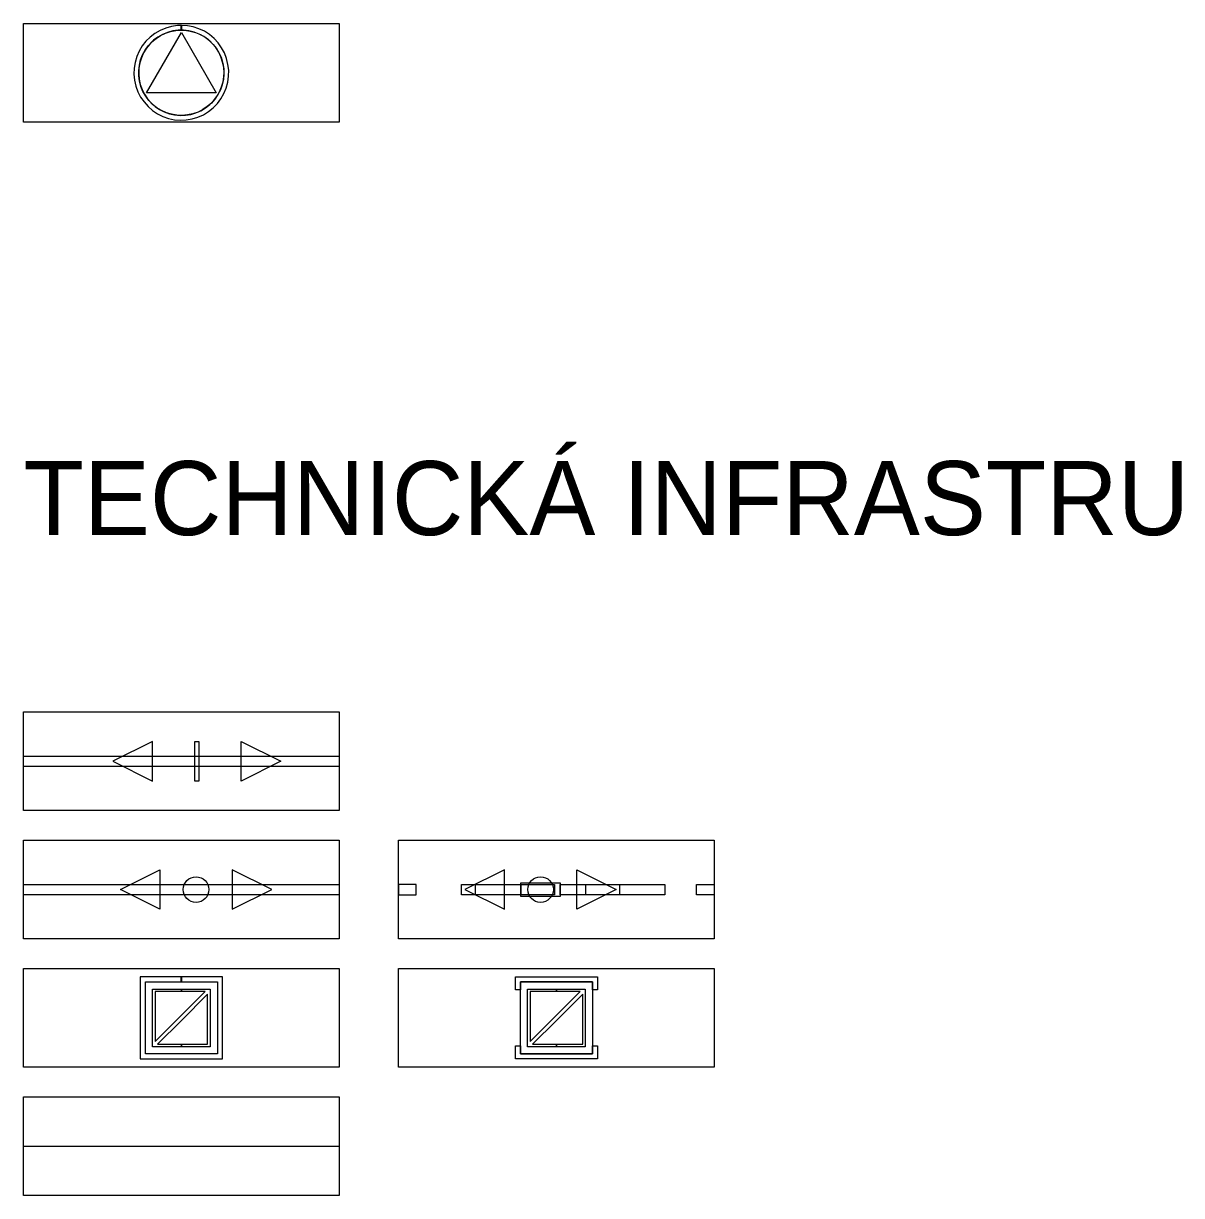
# Model space of a CAD drawing. Extents: x -477645 to -464995, y -1159281 to -1149080.
# Drawn here: x -466094.7 to -465801.3, y -1156175.7 to -1155878.8 of the extents above; entities that cross this region are included whole.
import ezdxf

# ---------------------------------------------------------------- set-up
doc = ezdxf.new("R2010")
doc.units = 0
for name, color, linetype in [('ložisk_nerost', 7, 'Continuous'), ('OP', 7, 'Continuous'), ('TRAFOSTANICE', 7, 'Continuous'), ('VN VZDUŠNÉ', 7, 'Continuous'), ('Vrstva 22_místní_vodovod_návrh', 7, 'Continuous'), ('Vrstva 60', 7, 'Continuous')]:
    doc.layers.add(name, color=color, linetype=linetype)

msp = doc.modelspace()

# ---------------------------------------------------------------- linework, layer by layer
at = {"layer": 'ložisk_nerost'}
for points in [[(-466054.7, -1155879.28), (-466055.7, -1155879.33), (-466057.2, -1155879.55), (-466058.66, -1155879.96), (-466060.06, -1155880.55), (-466061.37, -1155881.31), (-466062.58, -1155882.24), (-466063.66, -1155883.3), (-466064.59, -1155884.5), (-466065.37, -1155885.8), (-466065.98, -1155887.19), (-466066.41, -1155888.65), (-466066.65, -1155890.15), (-466066.69, -1155891.66), (-466066.55, -1155893.18), (-466066.22, -1155894.66), (-466065.7, -1155896.09), (-466065.01, -1155897.44), (-466064.15, -1155898.69), (-466063.14, -1155899.82), (-466062, -1155900.82), (-466060.74, -1155901.67), (-466059.38, -1155902.35), (-466057.95, -1155902.85), (-466056.46, -1155903.17), (-466054.95, -1155903.3), (-466053.44, -1155903.23), (-466051.94, -1155902.98), (-466050.49, -1155902.54), (-466049.1, -1155901.92), (-466047.8, -1155901.13), (-466046.62, -1155900.18), (-466045.56, -1155899.09), (-466044.65, -1155897.88), (-466043.9, -1155896.56), (-466043.32, -1155895.15), (-466042.93, -1155893.69), (-466042.72, -1155892.18), (-466042.7, -1155890.67), (-466042.88, -1155889.16), (-466043.24, -1155887.68), (-466043.79, -1155886.27), (-466044.51, -1155884.93), (-466045.39, -1155883.7), (-466046.42, -1155882.58), (-466047.59, -1155881.61), (-466048.87, -1155880.79), (-466050.24, -1155880.14), (-466051.68, -1155879.67), (-466053.17, -1155879.38), (-466054.69, -1155879.28)], [(-466043.88, -1155891.29), (-466043.97, -1155889.93), (-466044.23, -1155888.59), (-466044.65, -1155887.29), (-466045.24, -1155886.05), (-466045.98, -1155884.9), (-466046.85, -1155883.85), (-466047.85, -1155882.92), (-466048.96, -1155882.13), (-466050.17, -1155881.48), (-466051.44, -1155880.99), (-466052.77, -1155880.66), (-466054.12, -1155880.5), (-466055.49, -1155880.51), (-466056.84, -1155880.7), (-466058.16, -1155881.06), (-466059.43, -1155881.58), (-466060.61, -1155882.25), (-466061.71, -1155883.07), (-466062.69, -1155884.02), (-466063.54, -1155885.09), (-466064.25, -1155886.26), (-466064.81, -1155887.5), (-466065.21, -1155888.81), (-466065.44, -1155890.16), (-466065.5, -1155891.52), (-466065.38, -1155892.88), (-466065.1, -1155894.22), (-466064.64, -1155895.51), (-466064.03, -1155896.73), (-466063.27, -1155897.87), (-466062.37, -1155898.9), (-466061.35, -1155899.8), (-466060.23, -1155900.58), (-466059.01, -1155901.2), (-466057.73, -1155901.67), (-466056.39, -1155901.97), (-466055.03, -1155902.1), (-466053.67, -1155902.05), (-466052.32, -1155901.84), (-466051.01, -1155901.45), (-466049.75, -1155900.91), (-466048.58, -1155900.21), (-466047.5, -1155899.36), (-466046.54, -1155898.39), (-466045.71, -1155897.31), (-466045.03, -1155896.13), (-466044.49, -1155894.87), (-466044.12, -1155893.55), (-466043.92, -1155892.2), (-466043.88, -1155891.29)], [(-466054.69, -1155880.48), (-466053.79, -1155880.52), (-466052.44, -1155880.72), (-466051.12, -1155881.09), (-466049.86, -1155881.62), (-466048.68, -1155882.31), (-466047.6, -1155883.14), (-466046.63, -1155884.1), (-466045.78, -1155885.18), (-466045.08, -1155886.35), (-466044.53, -1155887.6), (-466044.15, -1155888.91), (-466043.93, -1155890.26), (-466043.89, -1155891.63), (-466044.02, -1155892.99), (-466044.32, -1155894.32), (-466044.78, -1155895.61), (-466045.41, -1155896.82), (-466046.18, -1155897.95), (-466047.09, -1155898.97), (-466048.12, -1155899.87), (-466049.25, -1155900.63), (-466050.47, -1155901.24), (-466051.76, -1155901.7), (-466053.1, -1155901.98), (-466054.46, -1155902.1), (-466055.82, -1155902.04), (-466057.17, -1155901.81), (-466058.48, -1155901.42), (-466059.73, -1155900.86), (-466060.89, -1155900.15), (-466061.96, -1155899.29), (-466062.91, -1155898.31), (-466063.73, -1155897.22), (-466064.41, -1155896.03), (-466064.93, -1155894.77), (-466065.28, -1155893.45), (-466065.47, -1155892.1), (-466065.49, -1155890.73), (-466065.33, -1155889.37), (-466065, -1155888.04), (-466064.51, -1155886.77), (-466063.86, -1155885.57), (-466063.06, -1155884.46), (-466062.13, -1155883.46), (-466061.09, -1155882.58), (-466059.94, -1155881.84), (-466058.7, -1155881.26), (-466057.4, -1155880.83), (-466056.06, -1155880.57), (-466054.7, -1155880.48)], [(-466054.69, -1155881.13), (-466045.89, -1155896.37), (-466063.49, -1155896.37), (-466054.69, -1155881.13)], [(-466054.7, -1155880.48), (-466054.7, -1155879.28)], [(-466054.69, -1155879.28), (-466054.69, -1155880.48)], [(-465970.09, -1156123.61), (-465970.09, -1156120.28)], [(-465970.09, -1156120.28), (-465952.62, -1156120.28)], [(-465968.81, -1156121.56), (-465950.57, -1156121.56), (-465950.57, -1156139.8), (-465968.81, -1156139.8), (-465968.81, -1156121.56)], [(-465952.62, -1156121.56), (-465968.81, -1156121.56), (-465968.81, -1156123.61)], [(-465952.62, -1156120.28), (-465949.29, -1156120.28), (-465949.29, -1156123.61)], [(-465950.57, -1156123.61), (-465950.57, -1156121.56), (-465952.62, -1156121.56)], [(-465968.81, -1156123.61), (-465970.09, -1156123.61)], [(-465966.98, -1156130.68), (-465966.98, -1156123.39), (-465959.69, -1156123.39)], [(-465959.69, -1156124.02), (-465966.35, -1156124.02)], [(-465966.35, -1156124.02), (-465966.35, -1156130.68)], [(-465960.33, -1156130.68), (-465953.67, -1156124.02)], [(-465959.69, -1156123.39), (-465959.69, -1156124.02)], [(-465953.03, -1156124.66), (-465959.69, -1156131.32)], [(-465959.66, -1156124.02), (-465959.66, -1156123.39)], [(-465959.66, -1156123.39), (-465952.4, -1156123.39), (-465952.4, -1156130.68)], [(-465953.67, -1156124.02), (-465959.66, -1156124.02)], [(-465953.03, -1156130.68), (-465953.03, -1156124.66)], [(-465949.29, -1156123.61), (-465950.57, -1156123.61)], [(-465959.69, -1156137.97), (-465966.98, -1156137.97), (-465966.98, -1156130.68)], [(-465966.35, -1156130.68), (-465966.35, -1156136.69)], [(-465966.35, -1156136.69), (-465960.33, -1156130.68)], [(-465952.4, -1156130.68), (-465952.4, -1156137.97), (-465959.66, -1156137.97)], [(-465953.03, -1156137.34), (-465953.03, -1156130.68)], [(-465959.69, -1156131.32), (-465965.71, -1156137.34)], [(-465966.76, -1156141.08), (-465970.09, -1156141.08), (-465970.09, -1156137.75)], [(-465970.09, -1156137.75), (-465968.81, -1156137.75)], [(-465968.81, -1156137.75), (-465968.81, -1156139.8), (-465952.62, -1156139.8)], [(-465949.29, -1156137.75), (-465949.29, -1156141.08), (-465966.76, -1156141.08)], [(-465965.71, -1156137.34), (-465959.69, -1156137.34)], [(-465959.69, -1156137.34), (-465959.69, -1156137.97)], [(-465959.66, -1156137.34), (-465953.03, -1156137.34)], [(-465959.66, -1156137.97), (-465959.66, -1156137.34)], [(-465952.62, -1156139.8), (-465950.57, -1156139.8), (-465950.57, -1156137.75)], [(-465950.57, -1156137.75), (-465949.29, -1156137.75)]]:
    msp.add_lwpolyline(points, dxfattribs=at)
at = {"layer": 'OP'}
msp.add_line((-466094.69, -1156163.18), (-466014.69, -1156163.18), dxfattribs=at)
at = {"layer": 'TRAFOSTANICE'}
for points in [[(-466054.72, -1156120.28), (-466065.09, -1156120.28), (-466065.09, -1156141.08), (-466044.29, -1156141.08), (-466044.29, -1156120.28), (-466054.69, -1156120.28)], [(-466063.81, -1156121.56), (-466045.57, -1156121.56), (-466045.57, -1156139.8), (-466063.81, -1156139.8), (-466063.81, -1156121.56)], [(-466054.69, -1156121.56), (-466045.57, -1156121.56), (-466045.57, -1156139.8), (-466063.81, -1156139.8), (-466063.81, -1156121.56), (-466054.72, -1156121.56)], [(-466054.72, -1156121.56), (-466054.72, -1156120.28)], [(-466054.69, -1156120.28), (-466054.69, -1156121.56)], [(-466061.98, -1156130.68), (-466061.98, -1156123.39), (-466054.69, -1156123.39)], [(-466054.69, -1156124.02), (-466061.35, -1156124.02)], [(-466061.35, -1156124.02), (-466061.35, -1156130.68)], [(-466055.33, -1156130.68), (-466048.68, -1156124.02)], [(-466054.69, -1156123.39), (-466054.69, -1156124.02)], [(-466048.03, -1156124.66), (-466054.69, -1156131.32)], [(-466054.66, -1156124.02), (-466054.66, -1156123.39)], [(-466054.66, -1156123.39), (-466047.4, -1156123.39), (-466047.4, -1156130.68)], [(-466048.68, -1156124.02), (-466054.66, -1156124.02)], [(-466048.03, -1156130.68), (-466048.03, -1156124.66)], [(-466054.69, -1156137.97), (-466061.98, -1156137.97), (-466061.98, -1156130.68)], [(-466061.35, -1156130.68), (-466061.35, -1156136.7)], [(-466061.35, -1156136.7), (-466055.33, -1156130.68)], [(-466047.4, -1156130.68), (-466047.4, -1156137.97), (-466054.66, -1156137.97)], [(-466048.03, -1156137.34), (-466048.03, -1156130.68)], [(-466054.69, -1156131.32), (-466060.71, -1156137.34)], [(-466060.71, -1156137.34), (-466054.69, -1156137.34)], [(-466054.69, -1156137.34), (-466054.69, -1156137.97)], [(-466054.66, -1156137.34), (-466048.03, -1156137.34)], [(-466054.66, -1156137.97), (-466054.66, -1156137.34)]]:
    msp.add_lwpolyline(points, dxfattribs=at)
at = {"layer": 'VN VZDUŠNÉ'}
for p, q in [((-466062.03, -1156060.68), (-466072.03, -1156065.68)), ((-466062.03, -1156070.68), (-466062.03, -1156060.68)), ((-466039.53, -1156070.68), (-466039.53, -1156060.68)), ((-466039.53, -1156060.68), (-466029.53, -1156065.68)), ((-466072.03, -1156065.68), (-466062.03, -1156070.68)), ((-466029.53, -1156065.68), (-466039.53, -1156070.68))]:
    msp.add_line(p, q, dxfattribs=at)
for points in [[(-466050.28, -1156060.68), (-466050.28, -1156070.68), (-466051.28, -1156070.68)], [(-466051.28, -1156070.68), (-466051.28, -1156060.68)], [(-466051.28, -1156060.68), (-466050.28, -1156060.68)]]:
    msp.add_lwpolyline(points, dxfattribs=at)
msp.add_lwpolyline([(-466014.69, -1156066.98), (-466094.69, -1156066.98), (-466094.69, -1156064.38), (-466014.69, -1156064.38)], close=True, dxfattribs=at)
at = {"layer": 'Vrstva 22_místní_vodovod_návrh'}
for p, q in [((-466070.14, -1156098.18), (-466060.14, -1156093.18)), ((-466060.14, -1156093.18), (-466060.14, -1156103.18)), ((-466031.8, -1156098.18), (-466041.8, -1156093.18)), ((-466041.8, -1156093.18), (-466041.8, -1156103.18)), ((-465972.87, -1156093.18), (-465982.87, -1156098.18)), ((-465972.87, -1156103.18), (-465972.87, -1156093.18)), ((-465954.54, -1156103.18), (-465954.54, -1156093.18)), ((-465954.54, -1156093.18), (-465944.54, -1156098.18)), ((-466060.14, -1156103.18), (-466070.14, -1156098.18)), ((-466041.8, -1156103.18), (-466031.8, -1156098.18)), ((-465982.87, -1156098.18), (-465972.87, -1156103.18)), ((-465944.54, -1156098.18), (-465954.54, -1156103.18))]:
    msp.add_line(p, q, dxfattribs=at)
for points in [[(-466094.69, -1156096.88), (-466014.69, -1156096.88), (-466014.69, -1156099.48), (-466094.69, -1156099.48)], [(-465999.69, -1156099.48), (-465995.18, -1156099.48), (-465995.18, -1156096.88), (-465999.69, -1156096.88)], [(-465968.7, -1156099.48), (-465983.7, -1156099.48), (-465983.7, -1156096.88), (-465968.7, -1156096.88)], [(-465960.2, -1156099.48), (-465980.2, -1156099.48), (-465980.2, -1156096.88), (-465960.2, -1156096.88)], [(-465958.7, -1156099.93), (-465968.7, -1156099.93), (-465968.7, -1156096.43), (-465958.7, -1156096.43)], [(-465943.7, -1156099.48), (-465958.7, -1156099.48), (-465958.7, -1156096.88), (-465943.7, -1156096.88)], [(-465932.2, -1156099.48), (-465952.2, -1156099.48), (-465952.2, -1156096.88), (-465932.2, -1156096.88)], [(-465919.69, -1156099.48), (-465924.2, -1156099.48), (-465924.2, -1156096.88), (-465919.69, -1156096.88)]]:
    msp.add_lwpolyline(points, close=True, dxfattribs=at)
for centre in [(-466050.97, -1156098.18), (-465963.7, -1156098.18)]:
    msp.add_circle(centre, 3.25, dxfattribs=at)
at = {"layer": 'Vrstva 60'}
for points in [[(-466094.69, -1155878.79), (-466014.69, -1155878.79), (-466014.69, -1155903.79), (-466094.69, -1155903.79)], [(-466094.69, -1156053.18), (-466014.69, -1156053.18), (-466014.69, -1156078.18), (-466094.69, -1156078.18)], [(-466094.69, -1156085.68), (-466014.69, -1156085.68), (-466014.69, -1156110.68), (-466094.69, -1156110.68)], [(-465999.69, -1156085.68), (-465919.69, -1156085.68), (-465919.69, -1156110.68), (-465999.69, -1156110.68)], [(-466094.69, -1156118.18), (-466014.69, -1156118.18), (-466014.69, -1156143.18), (-466094.69, -1156143.18)], [(-465999.69, -1156118.18), (-465919.69, -1156118.18), (-465919.69, -1156143.18), (-465999.69, -1156143.18)], [(-466094.69, -1156150.68), (-466014.69, -1156150.68), (-466014.69, -1156175.68), (-466094.69, -1156175.68)]]:
    msp.add_lwpolyline(points, close=True, dxfattribs=at)

# ---------------------------------------------------------------- texts
msp.add_text('TECHNICKÁ INFRASTRUKTURA', height=18.75, dxfattribs=at).set_placement((-466094.69, -1156008.39))

doc.saveas('drawing.dxf')
